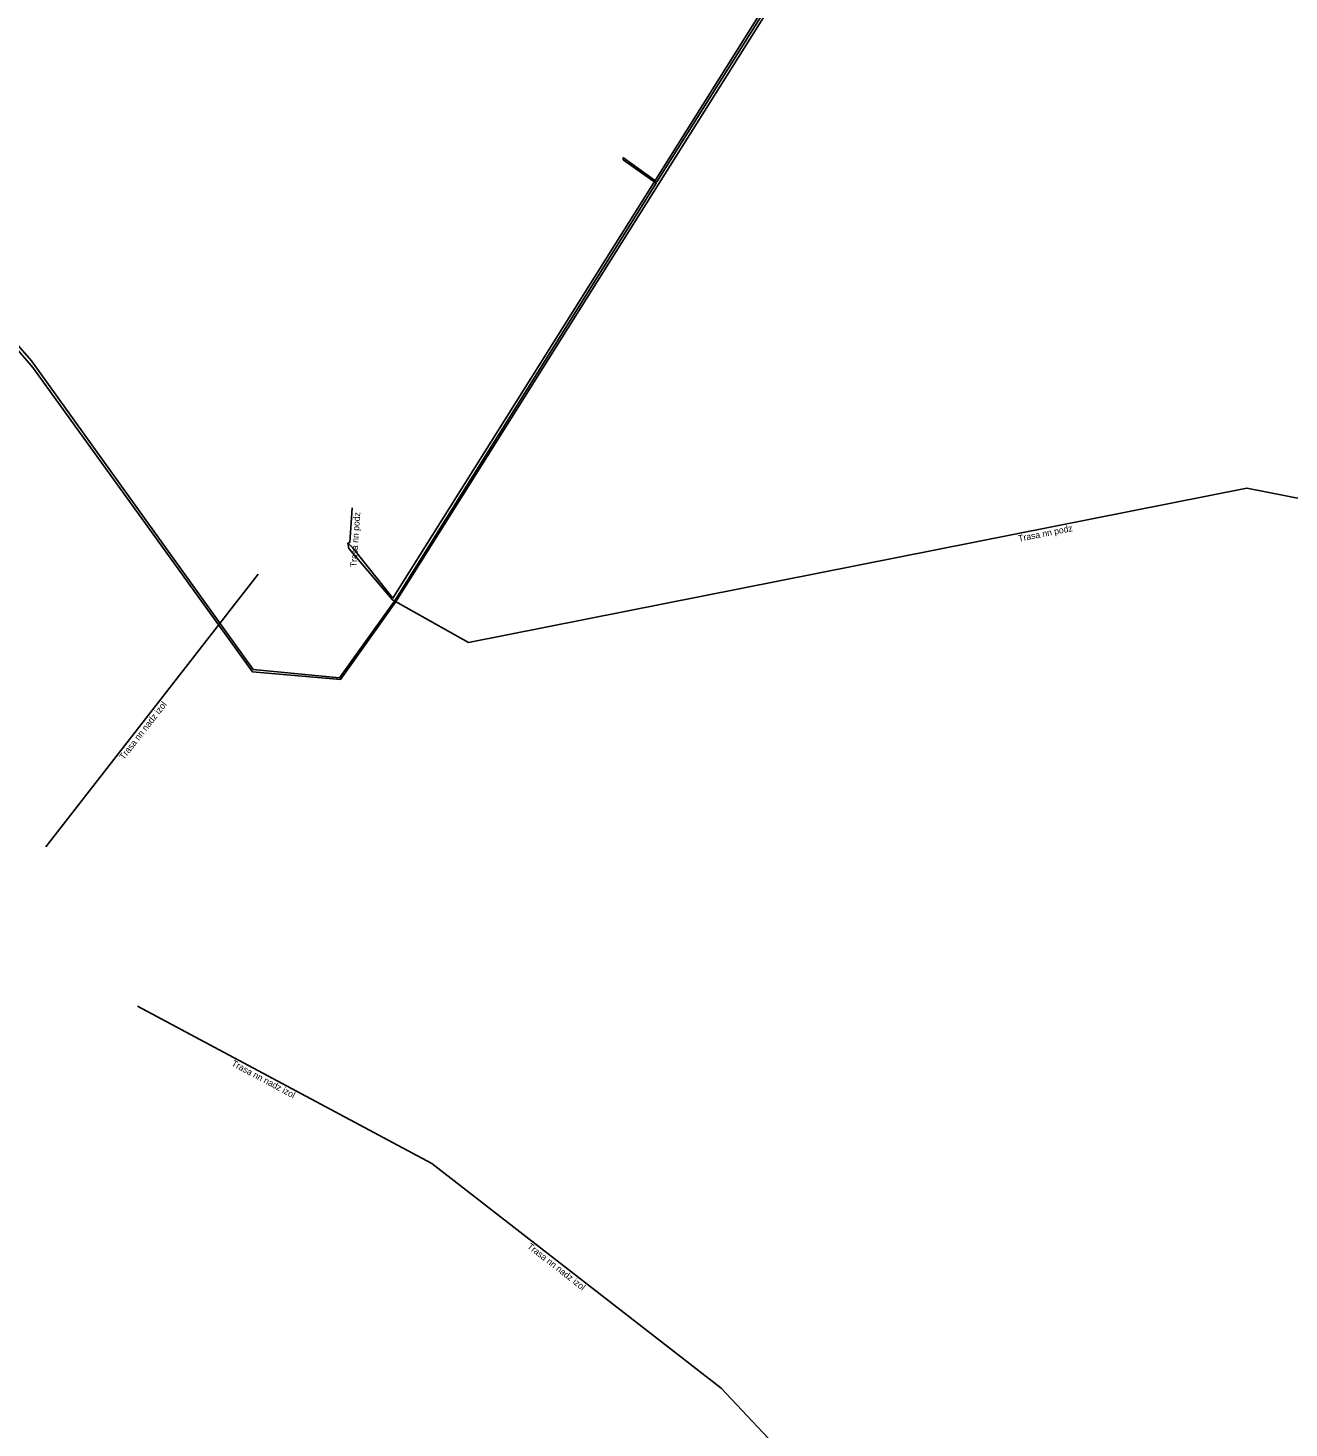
# Model space of a CAD drawing. Extents: x -875087 to -874407, y -1056142 to -1055396.
# Drawn here: x -874887.3 to -874789.7, y -1055889.5 to -1055781.1 of the extents above; entities that cross this region are included whole.
import ezdxf

# ---------------------------------------------------------------- set-up
doc = ezdxf.new("R2010")
doc.units = 0
doc.layers.add('Popiskový text - Ostatní atributy Trasy', color=7, linetype='Continuous')
doc.layers.add('Spojnice NN', color=7, linetype='Continuous')

msp = doc.modelspace()

# ---------------------------------------------------------------- linework, layer by layer
at = {"layer": 'Spojnice NN'}
for points in [[(-874671.63, -1055675.74), (-874670.33, -1055676.31), (-874664.47, -1055677.9), (-874660.5, -1055679.61), (-874654.24, -1055709.33), (-874658.68, -1055722.79), (-874695.05, -1055709.61), (-874743, -1055691.15), (-874768.77, -1055681.49), (-874774.59, -1055690.01), (-874781.56, -1055700.37), (-874783.65, -1055703.3), (-874788.62, -1055713.02), (-874797.64, -1055726.39), (-874799.59, -1055730.03), (-874808.94, -1055745.54), (-874820.99, -1055764.94), (-874838.65, -1055793.01), (-874841.25, -1055791.16), (-874841.27, -1055791.14)], [(-874845.94, -1055731.88), (-874845.02, -1055731.73), (-874841.56, -1055725.84), (-874809.29, -1055745.59), (-874821.17, -1055764.82), (-874859.09, -1055825.25), (-874862.21, -1055821.34), (-874862.58, -1055821)], [(-874841.27, -1055791.14), (-874841.27, -1055791.16), (-874841.26, -1055791.31), (-874838.71, -1055793.11), (-874858.97, -1055825.48), (-874863.22, -1055831.42), (-874869.9, -1055830.79), (-874887.06, -1055806.88), (-874895.84, -1055796.83), (-874904.11, -1055790.67), (-874918.62, -1055780.19), (-874921.67, -1055777.32), (-874933.9, -1055762.38), (-874954.73, -1055748.29), (-874954.29, -1055747.35), (-874954.2, -1055747.03)], [(-874895.86, -1055797.06), (-874886.96, -1055807.4), (-874869.97, -1055830.95), (-874863.15, -1055831.55), (-874858.88, -1055825.56), (-874838.49, -1055793.12), (-874820.8, -1055765.01)], [(-874755.56, -1055828), (-874754.94, -1055828.18), (-874754.41, -1055824.32), (-874792.98, -1055816.73), (-874853.23, -1055828.68), (-874859.13, -1055825.39), (-874862.5, -1055821.4), (-874862.58, -1055821)], [(-874862.58, -1055821), (-874862.43, -1055820.94), (-874862.25, -1055818.27), (-874862.26, -1055818.26)], [(-874869.52, -1055823.39), (-874885.95, -1055844.51)], [(-874878.87, -1055856.84), (-874856.07, -1055869.02)], [(-874856.07, -1055869.02), (-874833.69, -1055886.44)], [(-874833.69, -1055886.44), (-874817.96, -1055903.15)]]:
    msp.add_lwpolyline(points, dxfattribs=at)

# ---------------------------------------------------------------- texts
at = {"layer": 'Popiskový text - Ostatní atributy Trasy'}
for s, rotation, p in [('Trasa nn podz', 86.2227, (-874861.9, -1055822.87)), ('Trasa nn podz', 11.2214, (-874810.63, -1055820.89)), ('Trasa nn nadz izol', 52.1302, (-874879.92, -1055837.81)), ('Trasa nn nadz izol', 331.8916, (-874871.64, -1055861.43)), ('Trasa nn nadz izol', 322.0997, (-874848.74, -1055875.54))]:
    msp.add_text(s, height=0.5, rotation=rotation, dxfattribs=at).set_placement(p)

doc.saveas('drawing.dxf')
